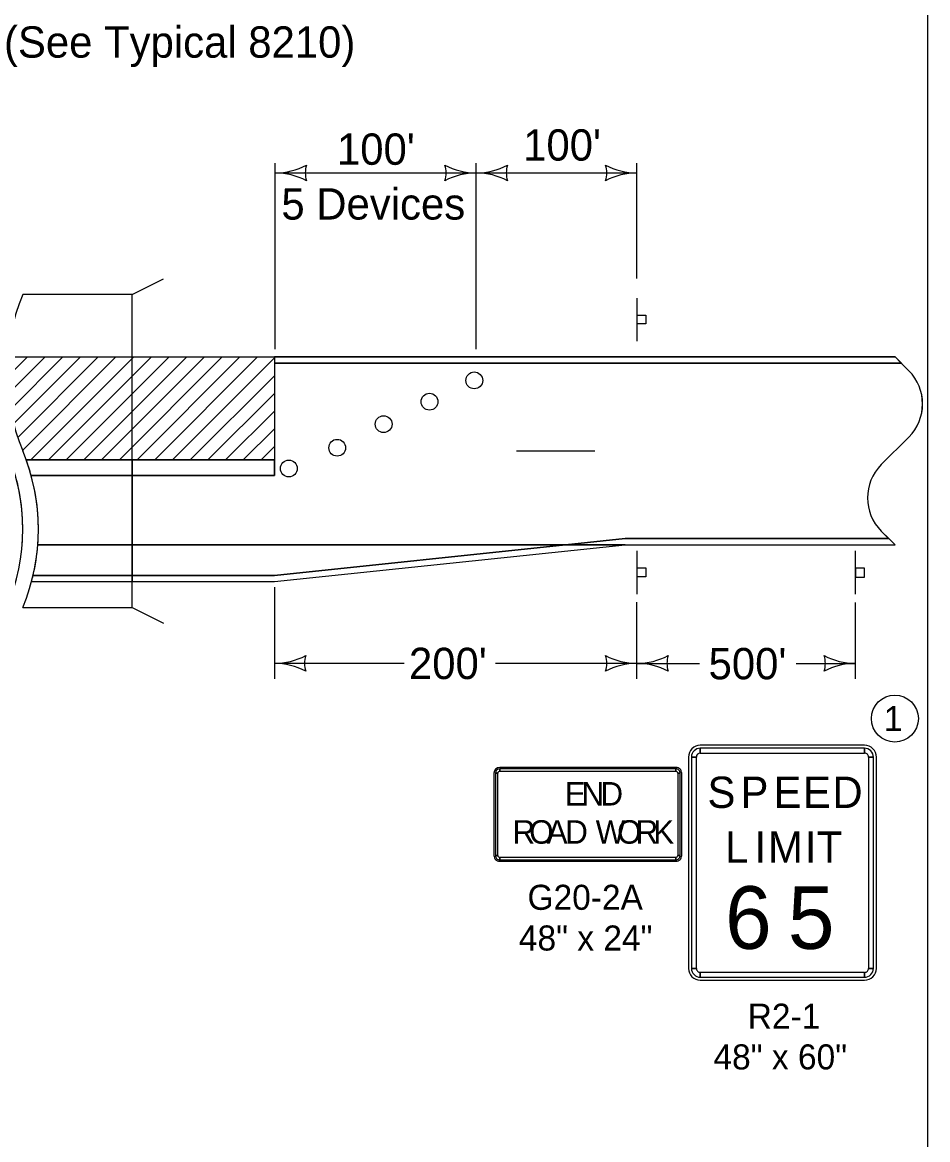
# Model space of a CAD drawing. Extents: x 10133 to 2270741, y 5363 to 1733450.
# Drawn here: x 27089 to 27668, y 8863 to 9577 of the extents above; entities that cross this region are included whole.
import ezdxf

# ---------------------------------------------------------------- set-up
doc = ezdxf.new("R2010")
doc.units = 0
for name, color, linetype in [('dsnNonPlotable', 7, 'Continuous'), ('dsnShtPlotShapeBatchPrint', 7, 'Continuous'), ('dsnStdBorder', 7, 'Continuous'), ('Level 12', 7, 'Continuous'), ('Level 2', 7, 'Continuous'), ('SheetBorder', 7, 'Continuous')]:
    doc.layers.add(name, color=color, linetype=linetype)

msp = doc.modelspace()

# ---------------------------------------------------------------- linework, layer by layer
at = {"layer": 'dsnNonPlotable'}
for p, q in [((27159.38, 9403.06), (27179.38, 9413.06)), ((27655.48, 9354.27), (27646.69, 9363.06)), ((27637.9, 9294.28), (27655.48, 9311.85)), ((27091.61, 9297.33), (27250.14, 9297.33)), ((27250.14, 9297.33), (27250.14, 9287.33)), ((27250.14, 9287.33), (27094.78, 9287.33)), ((27646.69, 9243.06), (27637.9, 9251.85)), ((27098.99, 9243.06), (27474.36, 9243.06)), ((27250.14, 9223.56), (27474.34, 9247.06)), ((27095.99, 9223.56), (27250.14, 9223.56)), ((27089.38, 9203.06), (27159.38, 9203.06)), ((27159.38, 9203.06), (27179.38, 9193.06))]:
    msp.add_line(p, q, dxfattribs=at)
for points in [[(27159.38, 9203.06), (27159.38, 9403.06), (27089.38, 9403.06)], [(27250.14, 9359.06), (27650.69, 9359.06)], [(27404.8, 9303.06), (27454.8, 9303.06)], [(27404.8, 9303.06), (27454.8, 9303.06)], [(27091.61, 9297.33), (27104.67, 9297.33)], [(27107.84, 9287.33), (27094.78, 9287.33)], [(27474.34, 9247.06), (27642.69, 9247.06)]]:
    msp.add_lwpolyline(points, dxfattribs=at)
for centre, radius, start, end in [((27209.38, 9353.06), 130, 157.38014, 202.61987), ((27634.27, 9333.06), 30, 315.00015, 44.99873), ((26959.38, 9253.06), 130, 337.38014, 22.61987), ((26969.38, 9253.06), 130, 337.38014, 22.61987), ((27659.12, 9273.06), 30, 135, 225)]:
    msp.add_arc(centre, radius, start, end, dxfattribs=at)
at = {"layer": 'dsnShtPlotShapeBatchPrint'}
msp.add_circle((27646.57, 9132.09), 15, dxfattribs=at)
at = {"layer": 'dsnStdBorder'}
for p, q in [((27481.75, 9400.6), (27481.75, 9373.1)), ((27079.41, 9350.08), (27092.39, 9363.06)), ((27080.09, 9339.45), (27103.7, 9363.06)), ((27081.52, 9329.56), (27115.02, 9363.06)), ((27083.57, 9320.3), (27126.33, 9363.06)), ((27086.17, 9311.59), (27137.64, 9363.06)), ((27089.25, 9303.36), (27148.96, 9363.06)), ((27094.54, 9297.33), (27160.27, 9363.06)), ((27105.85, 9297.33), (27171.59, 9363.06)), ((27117.17, 9297.33), (27182.9, 9363.06)), ((27128.48, 9297.33), (27194.21, 9363.06)), ((27139.79, 9297.33), (27205.53, 9363.06)), ((27151.11, 9297.33), (27216.84, 9363.06)), ((27162.42, 9297.33), (27228.15, 9363.06)), ((27173.73, 9297.33), (27239.47, 9363.06)), ((27250.14, 9363.06), (27250.14, 9297.33)), ((27185.05, 9297.33), (27250.14, 9362.42)), ((27196.36, 9297.33), (27250.14, 9351.1)), ((27207.68, 9297.33), (27250.14, 9339.79)), ((27218.99, 9297.33), (27250.14, 9328.48)), ((27230.3, 9297.33), (27250.14, 9317.16)), ((27241.62, 9297.33), (27250.14, 9305.85)), ((27159.38, 9297.33), (27159.38, 9287.33)), ((27250.14, 9287.33), (27250.14, 9297.33)), ((27159.38, 9287.33), (27250.14, 9287.33)), ((27250.14, 9223.56), (27474.34, 9247.06)), ((27474.34, 9247.06), (27642.69, 9247.06)), ((27481.75, 9239.15), (27481.75, 9211.65)), ((27621.39, 9211.65), (27621.39, 9239.15)), ((27627.24, 9115.02), (27522.24, 9115.02)), ((27522.24, 9110.02), (27522.24, 9113.14)), ((27627.24, 9113.14), (27627.24, 9110.02)), ((27514.74, 9107.52), (27514.74, 8972.52)), ((27516.61, 9107.52), (27519.74, 9107.52)), ((27629.74, 9107.52), (27632.86, 9107.52)), ((27634.74, 8972.52), (27634.74, 9107.52)), ((27506.65, 9100.95), (27394.15, 9100.95)), ((27394.15, 9098.45), (27394.15, 9100.01)), ((27506.65, 9100.01), (27506.65, 9098.45)), ((27390.4, 9097.2), (27390.4, 9044.7)), ((27391.34, 9097.2), (27392.9, 9097.2)), ((27507.9, 9097.2), (27509.47, 9097.2)), ((27510.4, 9044.7), (27510.4, 9097.2)), ((27392.9, 9044.7), (27391.34, 9044.7)), ((27394.15, 9041.88), (27394.15, 9043.45)), ((27506.65, 9043.45), (27506.65, 9041.88)), ((27509.47, 9044.7), (27507.9, 9044.7)), ((27394.15, 9040.95), (27506.65, 9040.95)), ((27519.74, 8972.52), (27516.61, 8972.52)), ((27632.86, 8972.52), (27629.74, 8972.52)), ((27522.24, 8966.89), (27522.24, 8970.02)), ((27522.24, 8965.02), (27627.24, 8965.02)), ((27627.24, 8970.02), (27627.24, 8966.89))]:
    msp.add_line(p, q, dxfattribs=at)
for points in [[(27481.85, 9384.15), (27481.85, 9389.78), (27487.47, 9389.78), (27487.47, 9384.15)], [(27481.85, 9222.7), (27481.85, 9228.33), (27487.47, 9228.33), (27487.47, 9222.7)], [(27621.48, 9228.1), (27621.48, 9222.47), (27627.11, 9222.47), (27627.11, 9228.1)], [(27627.24, 9113.14), (27522.24, 9113.14), (27522.24, 9110.02), (27627.24, 9110.02), (27627.24, 9113.14)], [(27516.61, 9107.52), (27516.61, 8972.52), (27519.74, 8972.52), (27519.74, 9107.52), (27516.61, 9107.52)], [(27632.86, 8972.52), (27632.86, 9107.52), (27629.74, 9107.52), (27629.74, 8972.52), (27632.86, 8972.52)], [(27506.65, 9100.01), (27394.15, 9100.01), (27394.15, 9098.45), (27506.65, 9098.45), (27506.65, 9100.01)], [(27391.34, 9097.2), (27391.34, 9044.7), (27392.9, 9044.7), (27392.9, 9097.2), (27391.34, 9097.2)], [(27509.47, 9044.7), (27509.47, 9097.2), (27507.9, 9097.2), (27507.9, 9044.7), (27509.47, 9044.7)], [(27394.15, 9041.88), (27506.65, 9041.88), (27506.65, 9043.45), (27394.15, 9043.45), (27394.15, 9041.88)], [(27522.24, 8966.89), (27627.24, 8966.89), (27627.24, 8970.02), (27522.24, 8970.02), (27522.24, 8966.89)]]:
    msp.add_lwpolyline(points, close=True, dxfattribs=at)
msp.add_lwpolyline([(27250.14, 9297.33), (27241.62, 9297.33), (27230.3, 9297.33), (27218.99, 9297.33), (27207.68, 9297.33), (27196.36, 9297.33), (27185.05, 9297.33), (27173.73, 9297.33), (27162.42, 9297.33), (27159.38, 9297.33)], dxfattribs=at)
for centre in [(27377.87, 9348.09), (27377.87, 9348.09), (27349.27, 9334.49), (27349.27, 9334.49), (27319.94, 9320.18), (27319.94, 9320.18), (27290.32, 9305.08), (27290.32, 9305.08), (27259.36, 9291.85), (27259.36, 9291.85)]:
    msp.add_circle(centre, 5.37, dxfattribs=at)
for centre, radius, start, end in [((27522.24, 9107.52), 7.5, 90.00021, 179.99985), ((27522.24, 9107.52), 5.62, 90.00021, 179.99985), ((27627.24, 9107.52), 7.5, 0, 90.00021), ((27627.24, 9107.52), 5.62, 0, 90.00021), ((27522.24, 9107.52), 2.5, 90.00021, 179.99985), ((27627.24, 9107.52), 2.5, 0, 90.00021), ((27394.15, 9097.2), 3.75, 90.00021, 179.99985), ((27394.15, 9097.2), 2.81, 90.00021, 179.99985), ((27506.65, 9097.2), 3.75, 0, 90.00021), ((27506.65, 9097.2), 2.81, 0, 90.00021), ((27394.15, 9097.2), 1.25, 90.00021, 179.99985), ((27506.65, 9097.2), 1.25, 0, 90.00021), ((27394.15, 9044.7), 3.75, 179.99985, 270.00006), ((27394.15, 9044.7), 2.81, 179.99985, 270.00006), ((27394.15, 9044.7), 1.25, 179.99985, 270.00006), ((27506.65, 9044.7), 3.75, 270.00006, 0.00027), ((27506.65, 9044.7), 2.81, 270.00006, 0.00027), ((27506.65, 9044.7), 1.25, 270.00006, 0.00027), ((27522.24, 8972.52), 7.5, 179.99985, 270.00006), ((27522.24, 8972.52), 5.62, 179.99985, 270.00006), ((27522.24, 8972.52), 2.5, 179.99985, 270.00006), ((27627.24, 8972.52), 7.5, 270.00006, 0.00027), ((27627.24, 8972.52), 5.62, 270.00006, 0.00027), ((27627.24, 8972.52), 2.5, 270.00006, 0.00027)]:
    msp.add_arc(centre, radius, start, end, dxfattribs=at)
at = {"layer": 'Level 12'}
for p, q in [((27250.67, 9368.11), (27250.67, 9486.82)), ((27379.16, 9368.11), (27379.16, 9486.82)), ((27481.75, 9413.09), (27481.75, 9486.82)), ((27250.67, 9480.59), (27481.75, 9480.59)), ((27250.14, 9216.13), (27250.14, 9157.41)), ((27481.75, 9157.41), (27481.75, 9206.55)), ((27621.39, 9157.41), (27621.39, 9206.29)), ((27333.09, 9167.33), (27250.14, 9167.33)), ((27481.75, 9167.33), (27391.43, 9167.33)), ((27481.75, 9167.33), (27521.86, 9167.33)), ((27583.62, 9167.33), (27621.39, 9167.33))]:
    msp.add_line(p, q, dxfattribs=at)
for centre, radius, start, end in [((27250.67, 9523.09), 42.5, 270, 298.07249), ((27286.31, 9480.59), 16.42, 162.26665, 197.73335), ((27343.47, 9480.59), 16.42, 342.26665, 17.73335), ((27379.1, 9523.09), 42.5, 241.92751, 270), ((27379.1, 9523.09), 42.5, 270, 298.07249), ((27414.74, 9480.59), 16.42, 162.26665, 197.73335), ((27446.11, 9480.59), 16.42, 342.26665, 17.73335), ((27481.75, 9523.09), 42.5, 241.92751, 270), ((27250.67, 9438.09), 42.5, 61.92751, 90), ((27379.1, 9438.09), 42.5, 90, 118.07249), ((27379.1, 9438.09), 42.5, 61.92751, 90), ((27481.75, 9438.09), 42.5, 90, 118.07249), ((27250.14, 9209.83), 42.5, 270, 298.07249), ((27285.78, 9167.33), 16.42, 162.26665, 197.73335), ((27446.11, 9167.33), 16.42, 342.26665, 17.73335), ((27481.75, 9209.83), 42.5, 241.92751, 270), ((27481.75, 9209.83), 42.5, 270, 298.07249), ((27517.39, 9167.33), 16.42, 162.26665, 197.73335), ((27585.75, 9167.33), 16.42, 342.26665, 17.73335), ((27621.39, 9209.83), 42.5, 241.92751, 270), ((27250.14, 9124.83), 42.5, 61.92751, 90), ((27481.75, 9124.83), 42.5, 90, 118.07249), ((27481.75, 9124.83), 42.5, 61.92751, 90), ((27621.39, 9124.83), 42.5, 90, 118.07249)]:
    msp.add_arc(centre, radius, start, end, dxfattribs=at)
at = {"layer": 'Level 2'}
for p, q in [((27079.76, 9363.06), (27646.69, 9363.06)), ((27646.69, 9363.06), (27250.14, 9363.06)), ((27250.14, 9363.06), (27250.14, 9359.06)), ((27650.69, 9359.06), (27646.69, 9363.06)), ((27250.14, 9359.06), (27650.69, 9359.06)), ((27650.69, 9359.06), (27250.14, 9359.06)), ((27250.14, 9359.06), (27250.14, 9351.1)), ((27655.48, 9354.28), (27650.69, 9359.06)), ((27250.14, 9351.1), (27250.14, 9339.79)), ((27250.14, 9339.79), (27250.14, 9328.48)), ((27637.9, 9294.28), (27655.48, 9311.85)), ((27159.38, 9287.33), (27159.38, 9297.33)), ((27250.14, 9297.33), (27250.14, 9287.33)), ((27094.78, 9287.33), (27107.84, 9287.33)), ((27107.84, 9287.33), (27159.38, 9287.33)), ((27159.38, 9243.06), (27159.38, 9287.33)), ((27250.14, 9287.33), (27159.38, 9287.33)), ((27159.38, 9287.33), (27159.38, 9243.06)), ((27642.69, 9247.06), (27637.9, 9251.85)), ((27159.38, 9243.06), (27098.99, 9243.06)), ((27098.99, 9243.06), (27159.38, 9243.06)), ((27392.53, 9243.06), (27159.38, 9243.06)), ((27159.38, 9243.06), (27159.38, 9223.56)), ((27159.38, 9223.56), (27159.38, 9243.06)), ((27159.38, 9243.06), (27436.2, 9243.06)), ((27250.14, 9219.56), (27474.34, 9243.06)), ((27250.14, 9223.56), (27436.18, 9243.06)), ((27250.14, 9219.56), (27474.34, 9243.06)), ((27436.18, 9243.06), (27250.14, 9223.56)), ((27392.53, 9243.06), (27646.69, 9243.06)), ((27436.18, 9243.06), (27392.53, 9243.06)), ((27474.34, 9247.06), (27436.18, 9243.06)), ((27474.34, 9243.06), (27436.18, 9243.06)), ((27436.18, 9243.06), (27646.69, 9243.06)), ((27436.2, 9243.06), (27474.34, 9247.06)), ((27642.69, 9247.06), (27474.34, 9247.06)), ((27474.34, 9247.06), (27642.69, 9247.06)), ((27646.69, 9243.06), (27642.69, 9247.06)), ((27095.99, 9223.56), (27109.05, 9223.56)), ((27109.05, 9223.56), (27095.99, 9223.56)), ((27109.05, 9223.56), (27159.38, 9223.56)), ((27159.38, 9223.56), (27109.05, 9223.56)), ((27159.38, 9223.56), (27250.14, 9223.56)), ((27250.14, 9223.56), (27159.38, 9223.56)), ((27159.38, 9223.56), (27159.38, 9219.56)), ((27159.38, 9219.56), (27159.38, 9223.56)), ((27094.99, 9219.56), (27159.38, 9219.56)), ((27094.99, 9219.56), (27250.14, 9219.56)), ((27094.99, 9219.56), (27108.05, 9219.56)), ((27159.38, 9219.56), (27250.14, 9219.56))]:
    msp.add_line(p, q, dxfattribs=at)
for points in [[(27650.69, 9359.06), (27650.69, 9359.06)], [(27650.69, 9359.06), (27650.69, 9359.06)], [(27250.14, 9328.48), (27250.14, 9317.16), (27250.14, 9305.85), (27250.14, 9297.33)], [(27159.38, 9297.33), (27151.11, 9297.33), (27139.79, 9297.33), (27128.48, 9297.33), (27117.17, 9297.33), (27105.85, 9297.33), (27104.67, 9297.33), (27094.54, 9297.33), (27091.61, 9297.33)], [(27159.38, 9287.33), (27107.84, 9287.33), (27094.78, 9287.33)], [(27392.53, 9243.06), (27392.53, 9243.06)], [(27642.69, 9247.06), (27642.69, 9247.06)], [(27642.69, 9247.06), (27642.69, 9247.06)]]:
    msp.add_lwpolyline(points, dxfattribs=at)
for centre, radius, start, end in [((27634.26, 9333.06), 30, 315, 45), ((26969.38, 9253.06), 130, 15.28322, 19.90817), ((27659.12, 9273.06), 30, 135, 225), ((26959.38, 9253.06), 130, 355.58827, 15.28231), ((26969.38, 9253.06), 130, 355.58916, 15.28322), ((26969.38, 9253.06), 130, 346.88255, 355.58916), ((26969.38, 9253.06), 130, 345.06535, 346.88255)]:
    msp.add_arc(centre, radius, start, end, dxfattribs=at)
at = {"layer": 'SheetBorder'}
msp.add_lwpolyline([(24532.52, 9944.02), (27667.53, 9944.02), (27667.53, 7924.02), (24532.52, 7924.02)], close=True, dxfattribs=at)

# ---------------------------------------------------------------- texts
at = {"layer": 'dsnShtPlotShapeBatchPrint'}
msp.add_text('1', height=16, dxfattribs=at).set_placement((27639.58, 9124.09))
at = {"layer": 'dsnStdBorder'}
for s, height, p in [('E', 15, (27435.73, 9076.57)), ('N', 15, (27446.35, 9076.57)), ('D', 15, (27458.44, 9076.57)), ('S', 20, (27526.87, 9075.02)), ('P', 20, (27547.96, 9075.02)), ('E', 20, (27569.05, 9075.02)), ('E', 20, (27587.86, 9075.02)), ('D', 20, (27606.67, 9075.02)), ('R', 15, (27402.27, 9052.2)), ('O', 15, (27412.95, 9052.2)), ('A', 15, (27424.11, 9052.2)), ('D', 15, (27435.96, 9052.2)), ('W', 15, (27455.42, 9052.2)), ('O', 15, (27469.15, 9052.2)), ('R', 15, (27480.92, 9052.2)), ('K', 15, (27492.22, 9052.2)), ('L', 20, (27538.12, 9040.02)), ('I', 20, (27556.93, 9040.02)), ('M', 20, (27565.52, 9040.02)), ('I', 20, (27589.11, 9040.02)), ('T', 20, (27596.67, 9040.02)), ('G20-2A', 16, (27411.87, 9009.95)), ('6', 40, (27538.12, 8985.02)), ('5', 40, (27578.24, 8985.02)), ('48" x 24"', 16, (27406.34, 8983.95)), ('R2-1', 16, (27552.57, 8934.02)), ('48" x 60"', 16, (27530.67, 8908.02))]:
    msp.add_text(s, height=height, dxfattribs=at).set_placement(p)
at = {"layer": 'Level 12'}
for s, p in [('(See Typical 8210)', (27077.41, 9554.22)), ("100'", (27290.13, 9485.81)), ("100'", (27409.09, 9488.46)), ('5 Devices', (27254.63, 9450.81)), ("200'", (27336.13, 9157.33)), ("500'", (27527.56, 9157.2))]:
    msp.add_text(s, height=20, dxfattribs=at).set_placement(p)

doc.saveas('drawing.dxf')
